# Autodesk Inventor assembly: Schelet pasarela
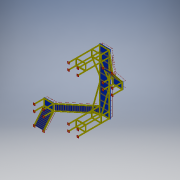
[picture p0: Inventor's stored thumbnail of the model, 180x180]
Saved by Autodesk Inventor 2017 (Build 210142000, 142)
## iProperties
Created: 2017-11
Part Number: Schelet pasarela
Document SubType Name: Assembly
Designer: iusti
Mass: 7.73602e+06 g
Surface Area: 1.54192e+06 cm^2
Volume: 1.29174e+06 cm^3
Density: 5.98884 g/cm^3
_SolveAssemblyDoc: Frame Generator Solve Assembly
_Version: 15.0.0
Author: iusti
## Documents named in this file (13)
- C:\Users\iusti\Desktop\pasarela\Schelet pasarela.iam
- C:\Users\iusti\Desktop\pasarela\Schelet pasarela.ipt
- C:\Users\iusti\Desktop\pasarela\Schelet pasarela\Frame\Frame0001.iam
- C:\Users\iusti\Desktop\pasarela\tabla.ipt
- C:\Users\iusti\Desktop\pasarela\talpa.ipt
- C:\Users\iusti\Desktop\pasarela\tabla1.ipt
- C:\Users\iusti\Desktop\pasarela\treapta.ipt
- C:\Users\iusti\Desktop\pasarela\treapta2.ipt
- C:\Users\iusti\Desktop\pasarela\Schelet pasarela\Frame\Frame0001_CPY1.iam
- C:\Users\iusti\Desktop\pasarela\talpa_CPY.ipt
- C:\Users\iusti\Desktop\pasarela\tabla1_CPY.ipt
- C:\Users\iusti\Desktop\pasarela\treapta_CPY.ipt
- C:\Users\iusti\Desktop\pasarela\treapta2_CPY.ipt
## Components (100 placed, 12 different names)
1. Schelet pasarela:1
2. Frame0001:1 [sub-assembly] — Mate:1, Flush:1, Flush:2, Mate:2, Mate:3, Mate:4, Mate:5, Flush:3, Flush:4, Flush:5, Flush:6, Flush:7, Flush:8, Flush:9, Flush:10, Mate:6, Mate:7, Mate:8, Mate:9, Flush:11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
3. tabla:1 — Mate:1, Flush:1, Flush:2, Flush:35, Flush:55
4. talpa:1 — Mate:4, Flush:3, Flush:4
5. talpa:2 — Mate:5, Flush:5, Flush:6
6. talpa:3 — Mate:3, Flush:7, Flush:8
7. talpa:4 — Mate:2, Flush:9, Flush:10
8. talpa:5 — Mate:6, Flush:15, Flush:16
9. talpa:6 — Mate:7, Flush:17, Flush:18
10. talpa:7 — Mate:9, Flush:11, Flush:12, Flush:54
11. talpa:8 — Mate:8, Flush:13, Flush:14
12. talpa:9 — Mate:10, Flush:19, Flush:20, Flush:30
13. talpa:10 — Mate:13, Flush:21, Flush:22
14. talpa:11 — Mate:11, Flush:23, Flush:24, Flush:29
15. talpa:12 — Mate:12, Flush:25, Flush:26
16. talpa:13 — Flush:27, Flush:28, Flush:30
17. talpa:14 — Flush:27, Flush:28, Mate:14, Flush:29, Mate:15
18. tabla1:1 — Mate:16, Flush:31, Flush:32, Flush:33
19. Frame0001_CPY1:1 [sub-assembly] — Flush:37, Flush:38, Mate:19, Flush:39, Flush:40, Mate:20, Flush:41, Flush:42, Mate:21, Flush:43, Flush:44, Mate:22, Mate:23, Mate:24, Flush:49, Flush:50, Mate:25, Flush:51, Mate:26, Mate:27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
20. talpa_CPY:1 — Flush:37, Flush:38, Mate:19, Flush:45
21. talpa_CPY:2 — Flush:39, Flush:40, Mate:20
22. talpa_CPY:3 — Flush:41, Flush:42, Mate:21, Flush:46, Flush:54
23. talpa_CPY:4 — Flush:43, Flush:44, Mate:22
24. talpa_CPY:5 — Flush:45, Flush:47, Flush:48
25. talpa_CPY:6 — Mate:23, Flush:46, Mate:24, Flush:47, Flush:48
26. tabla1_CPY:1 — Flush:49, Flush:50, Mate:25, Flush:52
27. treapta:1 — Mate:17, Flush:33, Flush:34
28. treapta:2
29. treapta:3
30. treapta:4
31. treapta:5
32. treapta:6
33. treapta:7
34. treapta:8
35. treapta:9
36. treapta:10
37. treapta:11
38. treapta:12
39. treapta2:1 — Mate:18, Flush:35, Flush:36
40. treapta2:2
41. treapta2:3
42. treapta2:4
43. treapta2:5
44. treapta2:6
45. treapta2:7
46. treapta2:8
47. treapta2:9
48. treapta2:10
49. treapta2:11
50. treapta2:12
51. treapta2:13
52. treapta2:14
53. treapta2:15
54. treapta2:16
55. treapta2:17
56. treapta2:18
57. treapta2:19
58. treapta2:20
59. treapta2:21
60. treapta2:22
61. treapta2:23
62. treapta2:24
63. treapta2:25
64. treapta_CPY:1 — Flush:51, Flush:52, Mate:26
65. treapta_CPY:2
66. treapta_CPY:3
67. treapta_CPY:4
68. treapta_CPY:5
69. treapta_CPY:6
70. treapta_CPY:7
71. treapta_CPY:8
72. treapta_CPY:9
73. treapta_CPY:10
74. treapta_CPY:11
75. treapta_CPY:12
76. treapta2_CPY:1 — Mate:27, Flush:55, Flush:56
77. treapta2_CPY:2
78. treapta2_CPY:3
79. treapta2_CPY:4
80. treapta2_CPY:5
81. treapta2_CPY:6
82. treapta2_CPY:7
83. treapta2_CPY:8
84. treapta2_CPY:9
85. treapta2_CPY:10
86. treapta2_CPY:11
87. treapta2_CPY:12
88. treapta2_CPY:13
89. treapta2_CPY:14
90. treapta2_CPY:15
91. treapta2_CPY:16
92. treapta2_CPY:17
93. treapta2_CPY:18
94. treapta2_CPY:19
95. treapta2_CPY:20
96. treapta2_CPY:21
97. treapta2_CPY:22
98. treapta2_CPY:23
99. treapta2_CPY:24
100. treapta2_CPY:25
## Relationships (84: Flush 56, Mate 28)
- Mate:1: Frame0001:1 ↔ tabla:1
- Flush:1: Frame0001:1 ↔ tabla:1
- Flush:2: Frame0001:1 ↔ tabla:1
- Mate:2: Frame0001:1 ↔ talpa:4
- Mate:3: Frame0001:1 ↔ talpa:3
- Mate:4: Frame0001:1 ↔ talpa:1
- Mate:5: Frame0001:1 ↔ talpa:2
- Flush:3: Frame0001:1 ↔ talpa:1
- Flush:4: Frame0001:1 ↔ talpa:1
- Flush:5: Frame0001:1 ↔ talpa:2
- Flush:6: Frame0001:1 ↔ talpa:2
- Flush:7: Frame0001:1 ↔ talpa:3
- Flush:8: Frame0001:1 ↔ talpa:3
- Flush:9: Frame0001:1 ↔ talpa:4
- Flush:10: Frame0001:1 ↔ talpa:4
- Mate:6: Frame0001:1 ↔ talpa:5
- Mate:7: Frame0001:1 ↔ talpa:6
- Mate:8: Frame0001:1 ↔ talpa:8
- Mate:9: Frame0001:1 ↔ talpa:7
- Flush:11: Frame0001:1 ↔ talpa:7
- Flush:12: Frame0001:1 ↔ talpa:7
- Flush:13: Frame0001:1 ↔ talpa:8
- Flush:14: Frame0001:1 ↔ talpa:8
- Flush:15: Frame0001:1 ↔ talpa:5
- Flush:16: Frame0001:1 ↔ talpa:5
- Flush:17: Frame0001:1 ↔ talpa:6
- Flush:18: Frame0001:1 ↔ talpa:6
- Mate:10: Frame0001:1 ↔ talpa:9
- Flush:19: Frame0001:1 ↔ talpa:9
- Flush:20: Frame0001:1 ↔ talpa:9
- Mate:11: Frame0001:1 ↔ talpa:11
- Mate:12: Frame0001:1 ↔ talpa:12
- Mate:13: Frame0001:1 ↔ talpa:10
- Flush:21: Frame0001:1 ↔ talpa:10
- Flush:22: Frame0001:1 ↔ talpa:10
- Flush:23: Frame0001:1 ↔ talpa:11
- Flush:24: Frame0001:1 ↔ talpa:11
- Flush:25: Frame0001:1 ↔ talpa:12
- Flush:26: Frame0001:1 ↔ talpa:12
- Flush:27: talpa:13 ↔ talpa:14
- Flush:28: talpa:13 ↔ talpa:14
- Mate:14: Frame0001:1 ↔ talpa:14
- Flush:29: talpa:11 ↔ talpa:14
- Flush:30: talpa:9 ↔ talpa:13
- Mate:15: Frame0001:1 ↔ talpa:14
- Mate:16: Frame0001:1 ↔ tabla1:1
- Flush:31: Frame0001:1 ↔ tabla1:1
- Flush:32: Frame0001:1 ↔ tabla1:1
- Mate:17: Frame0001:1 ↔ treapta:1
- Flush:33: tabla1:1 ↔ treapta:1
- Flush:34: Frame0001:1 ↔ treapta:1
- Mate:18: Frame0001:1 ↔ treapta2:1
- Flush:35: tabla:1 ↔ treapta2:1
- Flush:36: Frame0001:1 ↔ treapta2:1
- Flush:37: Frame0001_CPY1:1 ↔ talpa_CPY:1
- Flush:38: Frame0001_CPY1:1 ↔ talpa_CPY:1
- Mate:19: Frame0001_CPY1:1 ↔ talpa_CPY:1
- Flush:39: Frame0001_CPY1:1 ↔ talpa_CPY:2
- Flush:40: Frame0001_CPY1:1 ↔ talpa_CPY:2
- Mate:20: Frame0001_CPY1:1 ↔ talpa_CPY:2
- Flush:41: Frame0001_CPY1:1 ↔ talpa_CPY:3
- Flush:42: Frame0001_CPY1:1 ↔ talpa_CPY:3
- Mate:21: Frame0001_CPY1:1 ↔ talpa_CPY:3
- Flush:43: Frame0001_CPY1:1 ↔ talpa_CPY:4
- Flush:44: Frame0001_CPY1:1 ↔ talpa_CPY:4
- Mate:22: Frame0001_CPY1:1 ↔ talpa_CPY:4
- Flush:45: talpa_CPY:1 ↔ talpa_CPY:5
- Mate:23: Frame0001_CPY1:1 ↔ talpa_CPY:6
- Flush:46: talpa_CPY:3 ↔ talpa_CPY:6
- Mate:24: Frame0001_CPY1:1 ↔ talpa_CPY:6
- Flush:47: talpa_CPY:5 ↔ talpa_CPY:6
- Flush:48: talpa_CPY:5 ↔ talpa_CPY:6
- Flush:49: Frame0001_CPY1:1 ↔ tabla1_CPY:1
- Flush:50: Frame0001_CPY1:1 ↔ tabla1_CPY:1
- Mate:25: Frame0001_CPY1:1 ↔ tabla1_CPY:1
- Flush:51: Frame0001_CPY1:1 ↔ treapta_CPY:1
- Flush:52: tabla1_CPY:1 ↔ treapta_CPY:1
- Mate:26: Frame0001_CPY1:1 ↔ treapta_CPY:1
- Mate:27: Frame0001_CPY1:1 ↔ treapta2_CPY:1
- Mate:28: Frame0001:1 ↔ Frame0001_CPY1:1
- Flush:53: Frame0001:1 ↔ Frame0001_CPY1:1
- Flush:54: talpa:7 ↔ talpa_CPY:3
- Flush:55: tabla:1 ↔ treapta2_CPY:1
- Flush:56: Frame0001:1 ↔ treapta2_CPY:1
